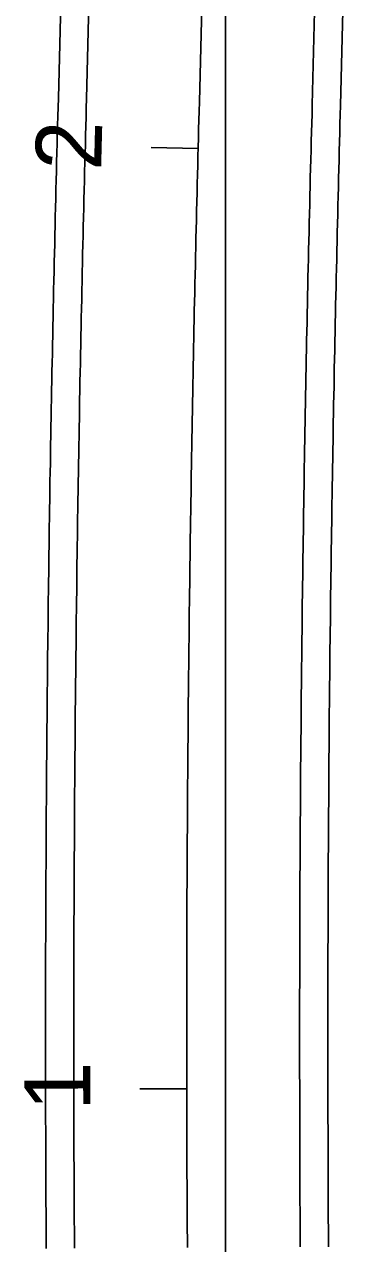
# Model space of a CAD drawing. Extents: x 2318076 to 2324211, y 613525 to 630327.
# Drawn here: x 2318859.1 to 2318895, y 615019.1 to 615148.8 of the extents above; entities that cross this region are included whole.
import ezdxf

# ---------------------------------------------------------------- set-up
doc = ezdxf.new("R2010")
doc.units = 0
for name, color, linetype in [('GE_P_CL_50', 7, 'Continuous'), ('PV_P_EOP', 7, 'Continuous'), ('PV_P_Shoulder', 7, 'Continuous'), ('SC_Scratch3', 7, 'Continuous')]:
    doc.layers.add(name, color=color, linetype=linetype)

msp = doc.modelspace()

# ---------------------------------------------------------------- linework, layer by layer
at = {"layer": 'GE_P_CL_50'}
for p, q in [((2318877.54, 615135.58), (2318872.54, 615135.7)), ((2318876.33, 615035.59), (2318871.33, 615035.58))]:
    msp.add_line(p, q, dxfattribs=at)
msp.add_lwpolyline([(2318876.39, 615018.71), (2318876.39, 615019.68), (2318876.38, 615020.65), (2318876.37, 615021.61), (2318876.37, 615022.58), (2318876.36, 615023.55), (2318876.36, 615024.51), (2318876.36, 615025.48), (2318876.35, 615026.45), (2318876.35, 615027.42), (2318876.34, 615028.38), (2318876.34, 615029.35), (2318876.34, 615030.32), (2318876.34, 615031.29), (2318876.33, 615032.25), (2318876.33, 615033.22), (2318876.33, 615034.19), (2318876.33, 615035.15), (2318876.33, 615036.12), (2318876.32, 615037.09), (2318876.32, 615038.06), (2318876.32, 615039.02), (2318876.32, 615039.99), (2318876.32, 615040.96), (2318876.32, 615041.92), (2318876.32, 615042.89), (2318876.32, 615043.86), (2318876.32, 615044.83), (2318876.32, 615045.79), (2318876.33, 615046.76), (2318876.33, 615047.73), (2318876.33, 615048.7), (2318876.33, 615049.66), (2318876.33, 615050.63), (2318876.34, 615051.6), (2318876.34, 615052.56), (2318876.34, 615053.53), (2318876.35, 615054.5), (2318876.35, 615055.47), (2318876.35, 615056.43), (2318876.36, 615057.4), (2318876.36, 615058.37), (2318876.37, 615059.33), (2318876.37, 615060.3), (2318876.38, 615061.27), (2318876.38, 615062.24), (2318876.39, 615063.2), (2318876.39, 615064.17), (2318876.4, 615065.14), (2318876.41, 615066.1), (2318876.41, 615067.07), (2318876.42, 615068.04), (2318876.43, 615069.01), (2318876.43, 615069.97), (2318876.44, 615070.94), (2318876.45, 615071.91), (2318876.46, 615072.87), (2318876.47, 615073.84), (2318876.48, 615074.81), (2318876.48, 615075.78), (2318876.49, 615076.74), (2318876.5, 615077.71), (2318876.51, 615078.68), (2318876.52, 615079.64), (2318876.53, 615080.61), (2318876.54, 615081.58), (2318876.55, 615082.54), (2318876.57, 615083.51), (2318876.58, 615084.48), (2318876.59, 615085.45), (2318876.6, 615086.41), (2318876.61, 615087.38), (2318876.62, 615088.35), (2318876.64, 615089.31), (2318876.65, 615090.28), (2318876.66, 615091.25), (2318876.68, 615092.21), (2318876.69, 615093.18), (2318876.7, 615094.15), (2318876.72, 615095.11), (2318876.73, 615096.08), (2318876.75, 615097.05), (2318876.76, 615098.02), (2318876.78, 615098.98), (2318876.79, 615099.95), (2318876.81, 615100.92), (2318876.82, 615101.88), (2318876.84, 615102.85), (2318876.86, 615103.82), (2318876.87, 615104.78), (2318876.89, 615105.75), (2318876.91, 615106.72), (2318876.92, 615107.68), (2318876.94, 615108.65), (2318876.96, 615109.62), (2318876.98, 615110.58), (2318877, 615111.55), (2318877.02, 615112.52), (2318877.03, 615113.48), (2318877.05, 615114.45), (2318877.07, 615115.42), (2318877.09, 615116.39), (2318877.11, 615117.35), (2318877.13, 615118.32), (2318877.15, 615119.29), (2318877.17, 615120.25), (2318877.2, 615121.22), (2318877.22, 615122.19), (2318877.24, 615123.15), (2318877.26, 615124.12), (2318877.28, 615125.09), (2318877.3, 615126.05), (2318877.33, 615127.02), (2318877.35, 615127.99), (2318877.37, 615128.95), (2318877.4, 615129.92), (2318877.42, 615130.88), (2318877.44, 615131.85), (2318877.47, 615132.82), (2318877.49, 615133.78), (2318877.52, 615134.75), (2318877.54, 615135.72), (2318877.57, 615136.68), (2318877.59, 615137.65), (2318877.62, 615138.62), (2318877.64, 615139.58), (2318877.67, 615140.55), (2318880.02, 615235.54)], dxfattribs=at)
at = {"layer": 'PV_P_EOP'}
for points in [[(2318864.39, 615018.64), (2318864.39, 615019.61), (2318864.38, 615020.58), (2318864.37, 615021.55), (2318864.37, 615022.52), (2318864.36, 615023.49), (2318864.36, 615024.46), (2318864.36, 615025.43), (2318864.35, 615026.4), (2318864.35, 615027.37), (2318864.34, 615028.34), (2318864.34, 615029.31), (2318864.34, 615030.28), (2318864.34, 615031.25), (2318864.33, 615032.22), (2318864.33, 615033.19), (2318864.33, 615034.16), (2318864.33, 615035.13), (2318864.33, 615036.1), (2318864.32, 615037.08), (2318864.32, 615038.05), (2318864.32, 615039.02), (2318864.32, 615039.99), (2318864.32, 615040.96), (2318864.32, 615041.93), (2318864.32, 615042.9), (2318864.32, 615043.87), (2318864.32, 615044.84), (2318864.32, 615045.81), (2318864.33, 615046.78), (2318864.33, 615047.75), (2318864.33, 615048.72), (2318864.33, 615049.69), (2318864.33, 615050.66), (2318864.34, 615051.63), (2318864.34, 615052.6), (2318864.34, 615053.57), (2318864.35, 615054.54), (2318864.35, 615055.51), (2318864.35, 615056.48), (2318864.36, 615057.45), (2318864.36, 615058.42), (2318864.37, 615059.39), (2318864.37, 615060.36), (2318864.38, 615061.33), (2318864.38, 615062.3), (2318864.39, 615063.27), (2318864.39, 615064.25), (2318864.4, 615065.22), (2318864.41, 615066.19), (2318864.41, 615067.16), (2318864.42, 615068.13), (2318864.43, 615069.1), (2318864.43, 615070.07), (2318864.44, 615071.04), (2318864.45, 615072.01), (2318864.46, 615072.98), (2318864.47, 615073.95), (2318864.48, 615074.92), (2318864.48, 615075.89), (2318864.49, 615076.86), (2318864.5, 615077.83), (2318864.51, 615078.8), (2318864.52, 615079.77), (2318864.53, 615080.74), (2318864.54, 615081.71), (2318864.56, 615082.68), (2318864.57, 615083.65), (2318864.58, 615084.62), (2318864.59, 615085.59), (2318864.6, 615086.56), (2318864.61, 615087.53), (2318864.63, 615088.5), (2318864.64, 615089.47), (2318864.65, 615090.44), (2318864.66, 615091.41), (2318864.68, 615092.38), (2318864.69, 615093.35), (2318864.71, 615094.32), (2318864.72, 615095.29), (2318864.73, 615096.26), (2318864.75, 615097.23), (2318864.76, 615098.2), (2318864.78, 615099.17), (2318864.79, 615100.14), (2318864.81, 615101.11), (2318864.83, 615102.08), (2318864.84, 615103.05), (2318864.86, 615104.02), (2318864.88, 615104.99), (2318864.89, 615105.96), (2318864.91, 615106.93), (2318864.93, 615107.9), (2318864.94, 615108.87), (2318864.96, 615109.84), (2318864.98, 615110.81), (2318865, 615111.78), (2318865.02, 615112.75), (2318865.04, 615113.72), (2318865.06, 615114.69), (2318865.08, 615115.66), (2318865.1, 615116.63), (2318865.12, 615117.6), (2318865.14, 615118.57), (2318865.16, 615119.54), (2318865.18, 615120.51), (2318865.2, 615121.48), (2318865.22, 615122.45), (2318865.24, 615123.42), (2318865.26, 615124.39), (2318865.29, 615125.36), (2318865.31, 615126.33), (2318865.33, 615127.3), (2318865.35, 615128.27), (2318865.38, 615129.24), (2318865.4, 615130.21), (2318865.42, 615131.18), (2318865.45, 615132.15), (2318865.47, 615133.12), (2318865.5, 615134.09), (2318865.52, 615135.06), (2318865.55, 615136.03), (2318865.57, 615137), (2318865.6, 615137.97), (2318865.62, 615138.94), (2318865.65, 615139.91), (2318865.67, 615140.86), (2318868.02, 615235.81)], [(2318888.39, 615018.79), (2318888.38, 615019.75), (2318888.38, 615020.71), (2318888.37, 615021.68), (2318888.37, 615022.64), (2318888.36, 615023.61), (2318888.36, 615024.57), (2318888.36, 615025.53), (2318888.35, 615026.5), (2318888.35, 615027.46), (2318888.34, 615028.43), (2318888.34, 615029.39), (2318888.34, 615030.35), (2318888.34, 615031.32), (2318888.33, 615032.28), (2318888.33, 615033.25), (2318888.33, 615034.21), (2318888.33, 615035.17), (2318888.33, 615036.14), (2318888.32, 615037.1), (2318888.32, 615038.07), (2318888.32, 615039.03), (2318888.32, 615039.99), (2318888.32, 615040.96), (2318888.32, 615041.92), (2318888.32, 615042.89), (2318888.32, 615043.85), (2318888.32, 615044.81), (2318888.32, 615045.78), (2318888.33, 615046.74), (2318888.33, 615047.71), (2318888.33, 615048.67), (2318888.33, 615049.64), (2318888.33, 615050.6), (2318888.34, 615051.56), (2318888.34, 615052.53), (2318888.34, 615053.49), (2318888.35, 615054.46), (2318888.35, 615055.42), (2318888.35, 615056.38), (2318888.36, 615057.35), (2318888.36, 615058.31), (2318888.37, 615059.27), (2318888.37, 615060.24), (2318888.38, 615061.2), (2318888.38, 615062.17), (2318888.39, 615063.13), (2318888.39, 615064.09), (2318888.4, 615065.06), (2318888.41, 615066.02), (2318888.41, 615066.99), (2318888.42, 615067.95), (2318888.43, 615068.91), (2318888.43, 615069.88), (2318888.44, 615070.84), (2318888.45, 615071.81), (2318888.46, 615072.77), (2318888.47, 615073.73), (2318888.47, 615074.7), (2318888.48, 615075.66), (2318888.49, 615076.63), (2318888.5, 615077.59), (2318888.51, 615078.55), (2318888.52, 615079.52), (2318888.53, 615080.48), (2318888.54, 615081.45), (2318888.55, 615082.41), (2318888.56, 615083.37), (2318888.58, 615084.34), (2318888.59, 615085.3), (2318888.6, 615086.26), (2318888.61, 615087.23), (2318888.62, 615088.19), (2318888.64, 615089.16), (2318888.65, 615090.12), (2318888.66, 615091.08), (2318888.68, 615092.05), (2318888.69, 615093.01), (2318888.7, 615093.97), (2318888.72, 615094.94), (2318888.73, 615095.9), (2318888.75, 615096.87), (2318888.76, 615097.83), (2318888.78, 615098.79), (2318888.79, 615099.76), (2318888.81, 615100.72), (2318888.82, 615101.68), (2318888.84, 615102.65), (2318888.85, 615103.61), (2318888.87, 615104.58), (2318888.89, 615105.54), (2318888.91, 615106.5), (2318888.92, 615107.47), (2318888.94, 615108.43), (2318888.96, 615109.39), (2318888.98, 615110.36), (2318888.99, 615111.32), (2318889.01, 615112.28), (2318889.03, 615113.25), (2318889.05, 615114.21), (2318889.07, 615115.18), (2318889.09, 615116.14), (2318889.11, 615117.1), (2318889.13, 615118.07), (2318889.15, 615119.03), (2318889.17, 615119.99), (2318889.19, 615120.96), (2318889.21, 615121.92), (2318889.24, 615122.88), (2318889.26, 615123.85), (2318889.28, 615124.81), (2318889.3, 615125.77), (2318889.32, 615126.74), (2318889.35, 615127.7), (2318889.37, 615128.66), (2318889.39, 615129.63), (2318889.42, 615130.59), (2318889.44, 615131.55), (2318889.46, 615132.52), (2318889.49, 615133.48), (2318889.51, 615134.44), (2318889.54, 615135.41), (2318889.56, 615136.37), (2318889.59, 615137.33), (2318889.61, 615138.3), (2318889.64, 615139.26), (2318889.67, 615140.24), (2318892.02, 615235.28)]]:
    msp.add_lwpolyline(points, dxfattribs=at)
at = {"layer": 'PV_P_Shoulder'}
for points in [[(2318861.39, 615018.62), (2318861.39, 615019.59), (2318861.38, 615020.56), (2318861.37, 615021.53), (2318861.37, 615022.5), (2318861.36, 615023.47), (2318861.36, 615024.45), (2318861.36, 615025.42), (2318861.35, 615026.39), (2318861.35, 615027.36), (2318861.34, 615028.33), (2318861.34, 615029.3), (2318861.34, 615030.27), (2318861.34, 615031.24), (2318861.33, 615032.22), (2318861.33, 615033.19), (2318861.33, 615034.16), (2318861.33, 615035.13), (2318861.33, 615036.1), (2318861.32, 615037.07), (2318861.32, 615038.04), (2318861.32, 615039.01), (2318861.32, 615039.99), (2318861.32, 615040.96), (2318861.32, 615041.93), (2318861.32, 615042.9), (2318861.32, 615043.87), (2318861.32, 615044.84), (2318861.32, 615045.81), (2318861.33, 615046.78), (2318861.33, 615047.75), (2318861.33, 615048.73), (2318861.33, 615049.7), (2318861.33, 615050.67), (2318861.34, 615051.64), (2318861.34, 615052.61), (2318861.34, 615053.58), (2318861.35, 615054.55), (2318861.35, 615055.52), (2318861.35, 615056.5), (2318861.36, 615057.47), (2318861.36, 615058.44), (2318861.37, 615059.41), (2318861.37, 615060.38), (2318861.38, 615061.35), (2318861.38, 615062.32), (2318861.39, 615063.29), (2318861.39, 615064.26), (2318861.4, 615065.24), (2318861.41, 615066.21), (2318861.41, 615067.18), (2318861.42, 615068.15), (2318861.43, 615069.12), (2318861.43, 615070.09), (2318861.44, 615071.06), (2318861.45, 615072.03), (2318861.46, 615073), (2318861.47, 615073.97), (2318861.48, 615074.95), (2318861.48, 615075.92), (2318861.49, 615076.89), (2318861.5, 615077.86), (2318861.51, 615078.83), (2318861.52, 615079.8), (2318861.53, 615080.77), (2318861.54, 615081.74), (2318861.56, 615082.71), (2318861.57, 615083.68), (2318861.58, 615084.66), (2318861.59, 615085.63), (2318861.6, 615086.6), (2318861.61, 615087.57), (2318861.63, 615088.54), (2318861.64, 615089.51), (2318861.65, 615090.48), (2318861.66, 615091.45), (2318861.68, 615092.42), (2318861.69, 615093.39), (2318861.71, 615094.37), (2318861.72, 615095.34), (2318861.73, 615096.31), (2318861.75, 615097.28), (2318861.76, 615098.25), (2318861.78, 615099.22), (2318861.79, 615100.19), (2318861.81, 615101.16), (2318861.83, 615102.13), (2318861.84, 615103.1), (2318861.86, 615104.07), (2318861.88, 615105.04), (2318861.89, 615106.02), (2318861.91, 615106.99), (2318861.93, 615107.96), (2318861.95, 615108.93), (2318861.96, 615109.9), (2318861.98, 615110.87), (2318862, 615111.84), (2318862.02, 615112.81), (2318862.04, 615113.78), (2318862.06, 615114.75), (2318862.08, 615115.72), (2318862.1, 615116.69), (2318862.12, 615117.66), (2318862.14, 615118.63), (2318862.16, 615119.61), (2318862.18, 615120.58), (2318862.2, 615121.55), (2318862.22, 615122.52), (2318862.24, 615123.49), (2318862.26, 615124.46), (2318862.29, 615125.43), (2318862.31, 615126.4), (2318862.33, 615127.37), (2318862.35, 615128.34), (2318862.38, 615129.31), (2318862.4, 615130.28), (2318862.42, 615131.25), (2318862.45, 615132.22), (2318862.47, 615133.19), (2318862.5, 615134.16), (2318862.52, 615135.13), (2318862.55, 615136.11), (2318862.57, 615137.08), (2318862.6, 615138.05), (2318862.62, 615139.02), (2318862.65, 615139.99), (2318862.68, 615140.94), (2318865.02, 615235.87)], [(2318891.39, 615018.8), (2318891.38, 615019.77), (2318891.38, 615020.73), (2318891.37, 615021.69), (2318891.37, 615022.66), (2318891.36, 615023.62), (2318891.36, 615024.58), (2318891.36, 615025.55), (2318891.35, 615026.51), (2318891.35, 615027.47), (2318891.34, 615028.44), (2318891.34, 615029.4), (2318891.34, 615030.36), (2318891.34, 615031.33), (2318891.33, 615032.29), (2318891.33, 615033.25), (2318891.33, 615034.22), (2318891.33, 615035.18), (2318891.33, 615036.14), (2318891.32, 615037.11), (2318891.32, 615038.07), (2318891.32, 615039.03), (2318891.32, 615040), (2318891.32, 615040.96), (2318891.32, 615041.92), (2318891.32, 615042.89), (2318891.32, 615043.85), (2318891.32, 615044.81), (2318891.32, 615045.78), (2318891.33, 615046.74), (2318891.33, 615047.7), (2318891.33, 615048.66), (2318891.33, 615049.63), (2318891.33, 615050.59), (2318891.34, 615051.55), (2318891.34, 615052.52), (2318891.34, 615053.48), (2318891.35, 615054.44), (2318891.35, 615055.41), (2318891.35, 615056.37), (2318891.36, 615057.33), (2318891.36, 615058.3), (2318891.37, 615059.26), (2318891.37, 615060.22), (2318891.38, 615061.19), (2318891.38, 615062.15), (2318891.39, 615063.11), (2318891.39, 615064.08), (2318891.4, 615065.04), (2318891.41, 615066), (2318891.41, 615066.97), (2318891.42, 615067.93), (2318891.43, 615068.89), (2318891.43, 615069.85), (2318891.44, 615070.82), (2318891.45, 615071.78), (2318891.46, 615072.74), (2318891.47, 615073.71), (2318891.47, 615074.67), (2318891.48, 615075.63), (2318891.49, 615076.6), (2318891.5, 615077.56), (2318891.51, 615078.52), (2318891.52, 615079.49), (2318891.53, 615080.45), (2318891.54, 615081.41), (2318891.55, 615082.38), (2318891.56, 615083.34), (2318891.58, 615084.3), (2318891.59, 615085.26), (2318891.6, 615086.23), (2318891.61, 615087.19), (2318891.62, 615088.15), (2318891.64, 615089.12), (2318891.65, 615090.08), (2318891.66, 615091.04), (2318891.68, 615092.01), (2318891.69, 615092.97), (2318891.7, 615093.93), (2318891.72, 615094.89), (2318891.73, 615095.86), (2318891.75, 615096.82), (2318891.76, 615097.78), (2318891.78, 615098.75), (2318891.79, 615099.71), (2318891.81, 615100.67), (2318891.82, 615101.63), (2318891.84, 615102.6), (2318891.85, 615103.56), (2318891.87, 615104.52), (2318891.89, 615105.49), (2318891.9, 615106.45), (2318891.92, 615107.41), (2318891.94, 615108.37), (2318891.96, 615109.34), (2318891.98, 615110.3), (2318891.99, 615111.26), (2318892.01, 615112.23), (2318892.03, 615113.19), (2318892.05, 615114.15), (2318892.07, 615115.11), (2318892.09, 615116.08), (2318892.11, 615117.04), (2318892.13, 615118), (2318892.15, 615118.97), (2318892.17, 615119.93), (2318892.19, 615120.89), (2318892.21, 615121.85), (2318892.23, 615122.82), (2318892.26, 615123.78), (2318892.28, 615124.74), (2318892.3, 615125.7), (2318892.32, 615126.67), (2318892.35, 615127.63), (2318892.37, 615128.59), (2318892.39, 615129.55), (2318892.42, 615130.52), (2318892.44, 615131.48), (2318892.46, 615132.44), (2318892.49, 615133.4), (2318892.51, 615134.37), (2318892.54, 615135.33), (2318892.56, 615136.29), (2318892.59, 615137.25), (2318892.61, 615138.22), (2318892.64, 615139.18), (2318892.66, 615140.16), (2318895.02, 615235.22)]]:
    msp.add_lwpolyline(points, dxfattribs=at)
at = {"layer": 'SC_Scratch3'}
msp.add_line((2318880.45, 614778.41), (2318880.45, 630327.22), dxfattribs=at)

# ---------------------------------------------------------------- texts
at = {"layer": 'GE_P_CL_50'}
for s, rotation, p in [('2', 88.5268, (2318867.22, 615133.23)), ('1', 90.0881, (2318866.08, 615033.28))]:
    msp.add_text(s, height=7, rotation=rotation, dxfattribs=at).set_placement(p)

doc.saveas('drawing.dxf')
